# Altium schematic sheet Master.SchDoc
size A; SheetNumber: 1; SheetTotal: 5
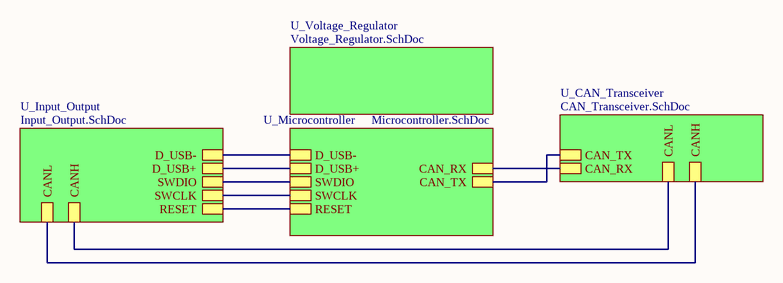
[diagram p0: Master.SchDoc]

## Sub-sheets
U_CAN_Transceiver = CAN_Transceiver.SchDoc: CANH, CANL, CAN_TX, CAN_RX
U_Input_Output = Input_Output.SchDoc: D_USB+, D_USB-, CANH, CANL, SWDIO, SWCLK, RESET
U_Microcontroller = Microcontroller.SchDoc: D_USB+, D_USB-, CAN_RX, CAN_TX, SWDIO, SWCLK, RESET
U_Voltage_Regulator = Voltage_Regulator.SchDoc: no entries

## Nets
(unnamed): sheet U_Input_Output/D_USB+, sheet U_Microcontroller/D_USB+
(unnamed): sheet U_Input_Output/D_USB-, sheet U_Microcontroller/D_USB-  [a separate net that carries the same name]
(unnamed): sheet U_Input_Output/CANH, sheet U_CAN_Transceiver/CANL  [a separate net that carries the same name]
(unnamed): sheet U_Input_Output/CANL, sheet U_CAN_Transceiver/CANH  [a separate net that carries the same name]
(unnamed): sheet U_Input_Output/SWDIO, sheet U_Microcontroller/SWDIO  [a separate net that carries the same name]
(unnamed): sheet U_Input_Output/SWCLK, sheet U_Microcontroller/SWCLK  [a separate net that carries the same name]
(unnamed): sheet U_Input_Output/RESET, sheet U_Microcontroller/RESET  [a separate net that carries the same name]
(unnamed): sheet U_Microcontroller/CAN_RX, sheet U_CAN_Transceiver/CAN_RX  [a separate net that carries the same name]
(unnamed): sheet U_Microcontroller/CAN_TX, sheet U_CAN_Transceiver/CAN_TX  [a separate net that carries the same name]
